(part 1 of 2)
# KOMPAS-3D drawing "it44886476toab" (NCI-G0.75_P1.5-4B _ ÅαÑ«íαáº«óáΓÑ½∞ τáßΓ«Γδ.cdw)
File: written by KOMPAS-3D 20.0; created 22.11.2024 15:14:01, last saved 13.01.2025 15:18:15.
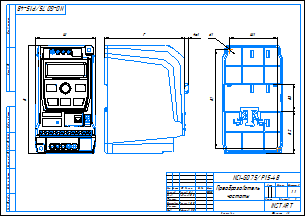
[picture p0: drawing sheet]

Sheet 1: A3, landscape

Document properties: Автор: admin; Полное имя файла: C:\Уралов Работа\Уралов (локальная)\ПЧ\! Китай 3Д-модель NCI\NCI 0.75-2.2 4B\NCI 0.75-2.2 4B.m3d

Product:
- Part/product: it44886476toab
    Масса: 2.32322
  - Body: Тело 17
      Масса: 0.0117014
  - Body: Тело 374
      Масса: 5.48304e-05
  - Body: Тело 265
      Масса: 1.32696e-05
  - Body: Тело 266
      Масса: 1.7366e-05
  - Body: Тело 267
      Масса: 1.7366e-05
  - Body: Тело 103
      Масса: 1.32696e-05
  - Body: Тело 573
      Масса: 4.06595e-05
  - Body: Тело 348
      Масса: 1.32696e-05
  - Body: Тело 270
      Масса: 1.7366e-05
  - Body: Тело 77
      Масса: 1.32696e-05
  - Body: Тело 244
      Масса: 1.65581e-05
  - Body: Тело 536
      Масса: 0.000158536
  - Body: Тело 377
      Масса: 1.65581e-05
  - Body: Тело 272
      Масса: 1.7366e-05
  - Body: Тело 273
      Масса: 5.48304e-05
  - Body: Тело 238
      Масса: 1.7366e-05
  - Body: Тело 274
      Масса: 1.7366e-05
  - Body: Тело 277
      Масса: 1.7366e-05
  - Body: Тело 530
      Масса: 5.61948e-05
  - Body: Тело 278
      Масса: 1.7366e-05
  - Body: Тело 282
      Масса: 1.7366e-05
  - Body: Тело 477
      Масса: 1.51773e-05
  - Body: Тело 526
      Масса: 5.61948e-05
  - Body: Тело 391
      Масса: 1.32696e-05
  - Body: Тело 285
      Масса: 5.48304e-05
  - Body: Тело 287
      Масса: 1.32696e-05
  - Body: Тело 290
      Масса: 0.000413213
  - Body: Тело 269
      Масса: 5.48304e-05
  - Body: Тело 292
      Масса: 1.7366e-05
  - Body: Тело 33
      Масса: 0.00516019
  - Body: Тело 252
      Масса: 5.48304e-05
  - Body: Тело 294
      Масса: 0.000413213
  - Body: Тело 297
      Масса: 3.64631e-05
  - Body: Тело 299
      Масса: 3.64028e-05
  - Body: Тело 283
      Масса: 1.7366e-05
  - Body: Тело 300
      Масса: 1.65581e-05
  - Body: Тело 303
      Масса: 1.65581e-05
  - Body: Тело 516
      Масса: 0.00507377
  - Body: Тело 384
      Масса: 5.48304e-05
  - Body: Тело 360
      Масса: 1.32696e-05
  - Body: Тело 347
      Масса: 1.32696e-05
  - Body: Тело 304
      Масса: 1.65581e-05
  - Body: Тело 307
      Масса: 0.000213463
  - Body: Тело 308
      Масса: 0.000413213
  - Body: Тело 180
      Масса: 1.32696e-05
  - Body: Тело 240
      Масса: 1.7366e-05
  - Body: Тело 309
      Масса: 1.32696e-05
  - Body: Тело 473
      Масса: 0.00425494
  - Body: Тело 311
      Масса: 5.48304e-05
  - Body: Тело 122
      Масса: 1.65581e-05
  - Body: Тело 560
      Масса: 1.65581e-05
  - Body: Тело 312
      Масса: 5.48304e-05
  - Body: Тело 317
      Масса: 1.32696e-05
  - Body: Тело 318
      Масса: 1.32696e-05
  - Body: Тело 321
      Масса: 1.32696e-05
  - Body: Тело 324
      Масса: 1.32696e-05
  - Body: Тело 480
      Масса: 1.51773e-05
  - Body: Тело 288
      Масса: 1.7366e-05
  - Body: Тело 293
      Масса: 5.48304e-05
  - Body: Тело 325
      Масса: 1.32696e-05
  - Body: Тело 99
      Масса: 1.65581e-05
  - Body: Тело 617
      Масса: 1.63919e-05
  - Body: Тело 327
      Масса: 1.32696e-05
  - Body: Тело 31
      Масса: 0.0078835
  - Body: Тело 100
      Масса: 1.65581e-05
  - Body: Тело 105
      Масса: 1.32696e-05
  - Body: Тело 328
      Масса: 1.7366e-05
  - Body: Тело 301
      Масса: 1.65581e-05
  - Body: Тело 331
      Масса: 1.7366e-05
  - Body: Тело 332
      Масса: 1.7366e-05
  - Body: Тело 446
      Масса: 0.000307437
  - Body: Тело 337
      Масса: 1.7366e-05
  - Body: Тело 338
      Масса: 1.7366e-05
  - Body: Тело 570
      Масса: 4.06595e-05
  - Body: Тело 340
      Масса: 1.32696e-05
  - Body: Тело 196
      Масса: 1.32696e-05
  - Body: Тело 357
      Масса: 1.65581e-05
  - Body: Тело 346
      Масса: 1.32696e-05
  - Body: Тело 335
      Масса: 1.32696e-05
  - Body: Тело 281
      Масса: 1.32696e-05
  - Body: Тело 362
      Масса: 1.32696e-05
  - Body: Тело 353
      Масса: 1.7366e-05
  - Body: Тело 355
      Масса: 5.48304e-05
  - Body: Тело 466
      Масса: 0.00829114
  - Body: Тело 358
      Масса: 5.48304e-05
  - Body: Тело 359
      Масса: 1.7366e-05
  - Body: Тело 286
      Масса: 1.7366e-05
  - Body: Тело 86
      Масса: 1.32696e-05
  - Body: Тело 310
      Масса: 1.7366e-05
  - Body: Тело 368
      Масса: 1.32696e-05
  - Body: Тело 370
      Масса: 1.32696e-05
  - Body: Тело 333
      Масса: 1.32696e-05
  - Body: Тело 628
      Масса: 1.51773e-05
  - Body: Тело 371
      Масса: 1.7366e-05
  - Body: Тело 75
      Масса: 1.32696e-05
  - Body: Тело 373
      Масса: 1.32696e-05
  - Body: Тело 375
      Масса: 1.32696e-05
  - Body: Тело 351
      Масса: 2.90876e-05
  - Body: Тело 76
      Масса: 1.65581e-05
  - Body: Тело 259
      Масса: 1.7366e-05
  - Body: Тело 378
      Масса: 0.000413213
  - Body: Тело 95
      Масса: 0.000935996
  - Body: Тело 372
      Масса: 1.7366e-05
  - Body: Тело 322
      Масса: 1.32696e-05
  - Body: Тело 380
      Масса: 1.32696e-05
  - Body: Тело 639
      Масса: 1.63919e-05
  - Body: Тело 385
      Масса: 1.32696e-05
  - Body: Тело 291
      Масса: 0.000213463
  - Body: Тело 386
      Масса: 1.32696e-05
  - Body: Тело 229
      Масса: 1.32696e-05
  - Body: Тело 388
      Масса: 1.32696e-05
  - Body: Тело 389
      Масса: 1.65581e-05
  - Body: Тело 93
      Масса: 3.83377e-05
  - Body: Тело 390
      Масса: 1.65581e-05
  - Body: Тело 143
      Масса: 1.32696e-05
  - Body: Тело 394
      Масса: 1.32696e-05
  - Body: Тело 395
      Масса: 1.32696e-05
  - Body: Тело 354
      Масса: 0.000213463
  - Body: Тело 396
      Масса: 1.7366e-05
  - Body: Тело 397
      Масса: 1.32696e-05
  - Body: Тело 398
      Масса: 1.65581e-05
  - Body: Тело 479
      Масса: 1.51773e-05
  - Body: Тело 402
      Масса: 1.7366e-05
  - Body: Тело 59
      Масса: 1.32696e-05
  - Body: Тело 339
      Масса: 1.32696e-05
  - Body: Тело 404
      Масса: 1.32696e-05
  - Body: Тело 89
      Масса: 0.00142218
  - Body: Тело 406
      Масса: 1.65581e-05
  - Body: Тело 393
      Масса: 1.32696e-05
  - Body: Тело 52
      Масса: 1.32696e-05
  - Body: Тело 407
      Масса: 5.48304e-05
  - Body: Тело 97
      Масса: 0.0015961
  - Body: Тело 410
      Масса: 5.48304e-05
  - Body: Тело 636
      Масса: 1.65581e-05
  - Body: Тело 412
      Масса: 1.7366e-05
  - Body: Тело 413
      Масса: 1.32696e-05
  - Body: Тело 414
      Масса: 1.32696e-05
  - Body: Тело 537
      Масса: 0.000158536
  - Body: Тело 415
      Масса: 1.7366e-05
  - Body: Тело 235
      Масса: 1.7366e-05
  - Body: Тело 419
      Масса: 1.32696e-05
  - Body: Тело 648
      Масса: 0.00426189
  - Body: Тело 420
      Масса: 1.7366e-05
  - Body: Тело 186
      Масса: 1.32696e-05
  - Body: Тело 422
      Масса: 5.48304e-05
  - Body: Тело 381
      Масса: 1.7366e-05
  - Body: Тело 423
      Масса: 1.32696e-05
  - Body: Тело 424
      Масса: 1.7366e-05
  - Body: Тело 98
      Масса: 1.65581e-05
  - Body: Тело 305
      Масса: 1.65581e-05
  - Body: Тело 425
      Масса: 1.32696e-05
  - Body: Тело 365
      Масса: 1.32696e-05
  - Body: Тело 271
      Масса: 1.32696e-05
  - Body: Тело 206
      Масса: 1.32696e-05
  - Body: Тело 429
      Масса: 0.146258
  - Body: Тело 334
      Масса: 1.7366e-05
  - Body: Тело 430
      Масса: 0.146258
  - Body: Тело 350
      Масса: 1.7366e-05
  - Body: Тело 345
      Масса: 1.32696e-05
  - Body: Тело 431
      Масса: 0.146258
  - Body: Тело 364
      Масса: 1.32696e-05
  - Body: Тело 329
      Масса: 1.32696e-05
  - Body: Тело 434
      Масса: 0.000355433
  - Body: Тело 5
      Масса: 0.000355433
  - Body: Тело 124
      Масса: 1.65581e-05
  - Body: Тело 344
      Масса: 1.32696e-05
  - Body: Тело 436
      Масса: 0.000355433
  - Body: Тело 439
      Масса: 0.00113358
  - Body: Тело 606
      Масса: 0.000137594
  - Body: Тело 323
      Масса: 1.32696e-05
  - Body: Тело 441
      Масса: 0.00113358
  - Body: Тело 442
      Масса: 0.000355433
  - Body: Тело 554
      Масса: 4.06595e-05
  - Body: Тело 444
      Масса: 0.000355433
  - Body: Тело 246
      Масса: 1.65581e-05
  - Body: Тело 445
      Масса: 0.00113358
  - Body: Тело 438
      Масса: 0.000355433
  - Body: Тело 106
      Масса: 1.32696e-05
  - Body: Тело 508
      Масса: 1.51773e-05
  - Body: Тело 577
      Масса: 1.7366e-05
  - Body: Тело 392
      Масса: 1.32696e-05
  - Body: Тело 193
      Масса: 1.32696e-05
  - Body: Тело 448
      Масса: 0.000307437
  - Body: Тело 481
      Масса: 1.51773e-05
  - Body: Тело 450
      Масса: 6.34685e-05
  - Body: Тело 222
      Масса: 1.32696e-05
  - Body: Тело 315
      Масса: 1.7366e-05
  - Body: Тело 452
      Масса: 1.63919e-05
  - Body: Тело 53
      Масса: 1.32696e-05
  - Body: Тело 401
      Масса: 1.32696e-05
  - Body: Тело 418
      Масса: 1.7366e-05
  - Body: Тело 517
      Масса: 0.00106884
  - Body: Тело 417
      Масса: 1.32696e-05
  - Body: Тело 453
      Масса: 1.63919e-05
  - Body: Тело 454
      Масса: 0.000382752
  - Body: Тело 428
      Масса: 0.146258
  - Body: Тело 455
      Масса: 1.51773e-05
  - Body: Тело 539
      Масса: 1.51773e-05
  - Body: Тело 457
      Масса: 1.51773e-05
  - Body: Тело 459
      Масса: 3.90329e-05
  - Body: Тело 557
      Масса: 0.00166679
  - Body: Тело 569
      Масса: 1.32696e-05
  - Body: Тело 578
      Масса: 1.32696e-05
  - Body: Тело 626
      Масса: 1.32696e-05
  - Body: Тело 134
      Масса: 1.32696e-05
  - Body: Тело 582
      Масса: 1.65581e-05
  - Body: Тело 203
      Масса: 1.32696e-05
  - Body: Тело 572
      Масса: 1.32696e-05
  - Body: Тело 567
      Масса: 1.32696e-05
  - Body: Тело 207
      Масса: 1.32696e-05
  - Body: Тело 645
      Масса: 1.32696e-05
  - Body: Тело 559
      Масса: 1.65581e-05
  - Body: Тело 152
      Масса: 1.32696e-05
  - Body: Тело 449
      Масса: 0.0658364
  - Body: Тело 316
      Масса: 1.32696e-05
  - Body: Тело 376
      Масса: 1.32696e-05
  - Body: Тело 575
      Масса: 1.32696e-05
  - Body: Тело 576
      Масса: 1.32696e-05
  - Body: Тело 85
      Масса: 1.32696e-05
  - Body: Тело 574
      Масса: 4.06595e-05
  - Body: Тело 399
      Масса: 1.32696e-05
  - Body: Тело 320
      Масса: 1.32696e-05
  - Body: Тело 275
      Масса: 1.7366e-05
  - Body: Тело 213
      Масса: 1.32696e-05
  - Body: Тело 625
      Масса: 1.32696e-05
  - Body: Тело 644
      Масса: 0.000158536
  - Body: Тело 584
      Масса: 4.06595e-05
  - Body: Тело 70
      Масса: 1.65581e-05
  - Body: Тело 588
      Масса: 1.32696e-05
  - Body: Тело 276
      Масса: 1.7366e-05
  - Body: Тело 363
      Масса: 1.32696e-05
  - Body: Тело 474
      Масса: 1.51773e-05
  - Body: Тело 548
      Масса: 2.98222e-05
  - Body: Тело 409
      Масса: 5.48304e-05
  - Body: Тело 472
      Масса: 0.00329327
  - Body: Тело 533
      Масса: 5.61948e-05
  - Body: Тело 647
      Масса: 0.00426189
  - Body: Тело 586
      Масса: 1.32696e-05
  - Body: Тело 262
      Масса: 1.7366e-05
  - Body: Тело 562
      Масса: 0.000382752
  - Body: Тело 379
      Масса: 1.32696e-05
  - Body: Тело 632
      Масса: 1.51773e-05
  - Body: Тело 565
      Масса: 4.06595e-05
  - Body: Тело 118
      Масса: 0.000413213
  - Body: Тело 597
      Масса: 7.12116e-06
  - Body: Тело 613
      Масса: 1.63919e-05
  - Body: Тело 387
      Масса: 1.32696e-05
  - Body: Тело 593
      Масса: 1.32696e-05
  - Body: Тело 408
      Масса: 5.48304e-05
  - Body: Тело 109
      Масса: 1.32696e-05
  - Body: Тело 163
      Масса: 1.32696e-05
  - Body: Тело 488
      Масса: 1.51773e-05
  - Body: Тело 367
      Масса: 1.32696e-05
  - Body: Тело 411
      Масса: 5.48304e-05
  - Body: Тело 583
      Масса: 4.06595e-05
  - Body: Тело 598
      Масса: 7.12116e-06
  - Body: Тело 551
      Масса: 0.000255388
  - Body: Тело 405
      Масса: 1.32696e-05
  - Body: Тело 619
      Масса: 1.32696e-05
  - Body: Тело 361
      Масса: 1.32696e-05
  - Body: Тело 589
      Масса: 1.32696e-05
  - Body: Тело 499
      Масса: 1.51773e-05
  - Body: Тело 440
      Масса: 0.000355433
  - Body: Тело 640
      Масса: 1.63919e-05
  - Body: Тело 150
      Масса: 1.32696e-05
  - Body: Тело 568
      Масса: 1.32696e-05
  - Body: Тело 194
      Масса: 1.32696e-05
  - Body: Тело 251
      Масса: 1.7366e-05
  - Body: Тело 342
      Масса: 0.00166679
  - Body: Тело 604
      Масса: 5.61948e-05
  - Body: Тело 650
      Масса: 0.00426189
  - Body: Тело 161
      Масса: 1.32696e-05
  - Body: Тело 611
      Масса: 0.000158536
  - Body: Тело 210
      Масса: 1.32696e-05
  - Body: Тело 540
      Масса: 1.51773e-05
  - Body: Тело 296
      Масса: 3.6965e-05
  - Body: Тело 601
      Масса: 5.61948e-05
  - Body: Тело 484
      Масса: 0.000158536
  - Body: Тело 622
      Масса: 1.32696e-05
  - Body: Тело 527
      Масса: 0.000141095
  - Body: Тело 624
      Масса: 1.32696e-05
  - Body: Тело 121
      Масса: 0.000413213
  - Body: Тело 600
      Масса: 5.61948e-05
  - Body: Тело 603
      Масса: 5.61948e-05
  - Body: Тело 607
      Масса: 1.32696e-05
  - Body: Тело 289
      Масса: 1.7366e-05
  - Body: Тело 471
      Масса: 0.00329327
  - Body: Тело 313
      Масса: 1.7366e-05
  - Body: Тело 591
      Масса: 7.12116e-06
  - Body: Тело 356
      Масса: 1.65581e-05
  - Body: Тело 306
      Масса: 1.65581e-05
  - Body: Тело 541
      Масса: 0.000158536
  - Body: Тело 511
      Масса: 1.51773e-05
  - Body: Тело 160
      Масса: 1.32696e-05
  - Body: Тело 566
      Масса: 1.32696e-05
  - Body: Тело 563
      Масса: 4.06595e-05
  - Body: Тело 638
      Масса: 1.7366e-05
  - Body: Тело 489
      Масса: 1.51773e-05
  - Body: Тело 456
      Масса: 1.51773e-05
  - Body: Тело 485
      Масса: 0.000158536
  - Body: Тело 284
      Масса: 1.7366e-05
  - Body: Тело 138
      Масса: 2.23009e-05
  - Body: Тело 225
      Масса: 1.32696e-05
  - Body: Тело 546
      Масса: 0.000255388
  - Body: Тело 113
      Масса: 0.000413213
  - Body: Тело 642
      Масса: 3.90329e-05
  - Body: Тело 618
      Масса: 1.63919e-05
  - Body: Тело 525
      Масса: 0.000213463
  - Body: Тело 164
      Масса: 1.32696e-05
  - Body: Тело 253
      Масса: 1.7366e-05
  - Body: Тело 561
      Масса: 1.65581e-05
  - Body: Тело 594
      Масса: 1.32696e-05
  - Body: Тело 482
      Масса: 1.51773e-05
  - Body: Тело 81
      Масса: 1.32696e-05
  - Body: Тело 280
      Масса: 1.32696e-05
  - Body: Тело 494
      Масса: 1.51773e-05
  - Body: Тело 641
      Масса: 3.90329e-05
  - Body: Тело 564
      Масса: 4.06595e-05
  - Body: Тело 633
      Масса: 1.51773e-05
  - Body: Тело 518
      Масса: 0.00166679
  - Body: Тело 620
      Масса: 1.7366e-05
  - Body: Тело 497
      Масса: 1.51773e-05
  - Body: Тело 151
      Масса: 1.65581e-05
  - Body: Тело 302
      Масса: 1.65581e-05
  - Body: Тело 110
      Масса: 1.32696e-05
  - Body: Тело 646
      Масса: 0.000137594
  - Body: Тело 264
      Масса: 1.7366e-05
  - Body: Тело 635
      Масса: 1.65581e-05
  - Body: Тело 608
      Масса: 0.00166679
  - Body: Тело 460
      Масса: 3.90329e-05
  - Body: Тело 403
      Масса: 1.7366e-05
  - Body: Тело 612
      Масса: 0.000158536
  - Body: Тело 492
      Масса: 1.51773e-05
  - Body: Тело 139
      Масса: 0.000194606
  - Body: Тело 400
      Масса: 1.7366e-05
  - Body: Тело 605
      Масса: 5.61948e-05
  - Body: Тело 623
      Масса: 1.32696e-05
  - Body: Тело 117
      Масса: 0.000413213
  - Body: Тело 185
      Масса: 1.32696e-05
  - Body: Тело 631
      Масса: 1.51773e-05
  - Body: Тело 580
      Масса: 1.32696e-05
  - Body: Тело 349
      Масса: 1.7366e-05
  - Body: Тело 621
      Масса: 1.32696e-05
  - Body: Тело 627
      Масса: 0.000255388
  - Body: Тело 531
      Масса: 5.61948e-05
  - Body: Тело 649
      Масса: 0.00426189
  - Body: Тело 585
      Масса: 4.06595e-05
  - Body: Тело 236
      Масса: 1.7366e-05
  - Body: Тело 513
      Масса: 1.51773e-05
  - Body: Тело 426
      Масса: 1.32696e-05
  - Body: Тело 341
      Масса: 0.00166679
  - Body: Тело 470
      Масса: 0.00329329
  - Body: Тело 382
      Масса: 5.48304e-05
  - Body: Тело 227
      Масса: 1.32696e-05
  - Body: Тело 476
      Масса: 1.51773e-05
  - Body: Тело 538
      Масса: 1.51773e-05
  - Body: Тело 596
      Масса: 1.32696e-05
  - Body: Тело 609
      Масса: 1.7366e-05
  - Body: Тело 610
      Масса: 0.00166679
  - Body: Тело 263
      Масса: 1.7366e-05
  - Body: Тело 629
      Масса: 1.51773e-05
  - Body: Тело 336
      Масса: 3.64028e-05
  - Body: Тело 495
      Масса: 1.51773e-05
  - Body: Тело 168
      Масса: 1.32696e-05
  - Body: Тело 298
      Масса: 3.64495e-05
  - Body: Тело 279
      Масса: 1.32696e-05
  - Body: Тело 72
      Масса: 1.65581e-05
  - Body: Тело 500
      Масса: 1.51773e-05
  - Body: Тело 505
      Масса: 1.51773e-05
  - Body: Тело 558
      Масса: 0.00726683
  - Body: Тело 630
      Масса: 1.51773e-05
  - Body: Тело 602
      Масса: 5.61948e-05
  - Body: Тело 556
      Масса: 0.00166679
  - Body: Тело 555
      Масса: 0.00166679
  - Body: Тело 634
      Масса: 1.51773e-05
  - Body: Тело 435
      Масса: 0.00113358
  - Body: Тело 416
      Масса: 1.7366e-05
  - Body: Тело 190
      Масса: 1.32696e-05
  - Body: Тело 330
      Масса: 1.7366e-05
  - Body: Тело 28
      Масса: 0.00135688
  - Body: Тело 553
      Масса: 4.06595e-05
  - Body: Тело 176
      Масса: 1.32696e-05
  - Body: Тело 552
      Масса: 4.06595e-05
  - Body: Тело 534
      Масса: 1.32696e-05
  - Body: Тело 595
      Масса: 1.32696e-05
  - Body: Тело 23
      Масса: 0.0243258
  - Body: Тело 247
      Масса: 1.7366e-05
  - Body: Тело 314
      Масса: 1.7366e-05
  - Body: Тело 126
      Масса: 0.000512664
  - Body: Тело 157
      Масса: 1.32696e-05
  - Body: Тело 550
      Масса: 0.000255388
  - Body: Тело 32
      Масса: 0.0135217
  - Body: Тело 592
      Масса: 7.12116e-06
  - Body: Тело 366
      Масса: 1.7366e-05
  - Body: Тело 504
      Масса: 1.51773e-05
  - Body: Тело 258
      Масса: 1.7366e-05
  - Body: Тело 421
      Масса: 1.7366e-05
  - Body: Тело 35
      Масса: 0.262997
  - Body: Тело 204
      Масса: 1.32696e-05
  - Body: Тело 549
      Масса: 0.000255388
  - Body: Тело 257
      Масса: 1.7366e-05
  - Body: Тело 614
      Масса: 1.63919e-05
  - Body: Тело 547
      Масса: 0.000255388
  - Body: Тело 41
      Масса: 0.0119524
  - Body: Тело 71
      Масса: 1.65581e-05
  - Body: Тело 506
      Масса: 1.51773e-05
  - Body: Тело 545
      Масса: 1.51773e-05
  - Body: Тело 145
      Масса: 1.32696e-05
  - Body: Тело 461
      Масса: 0.000404362
  - Body: Тело 502
      Масса: 1.51773e-05
  - Body: Тело 352
      Масса: 2.90876e-05
  - Body: Тело 120
      Масса: 0.000413213
  - Body: Тело 295
      Масса: 1.65581e-05
  - Body: Тело 544
      Масса: 0.000158536
  - Body: Тело 469
      Масса: 0.0113891
  - Body: Тело 146
      Масса: 1.32696e-05
  - Body: Тело 149
      Масса: 1.32696e-05
  - Body: Тело 615
      Масса: 1.63919e-05
  - Body: Тело 543
      Масса: 0.000158536
  - Body: Тело 542
      Масса: 0.000158536
  - Body: Тело 462
      Масса: 0.000404362
  - Body: Тело 616
      Масса: 1.63919e-05
  - Body: Тело 343
      Масса: 0.00166679
  - Body: Тело 532
      Масса: 5.61948e-05
  - Body: Тело 493
      Масса: 1.51773e-05
  - Body: Тело 529
      Масса: 5.61948e-05
  - Body: Тело 579
      Масса: 0.00017125
  - Body: Тело 200
      Масса: 1.32696e-05
  - Body: Тело 239
      Масса: 5.48304e-05
  - Body: Тело 443
      Масса: 0.00113358
  - Body: Тело 216
      Масса: 0.000280294
  - Body: Тело 468
      Масса: 0.0253857
  - Body: Тело 64
      Масса: 1.65581e-05
  - Body: Тело 528
      Масса: 0.000141095
  - Body: Тело 599
      Масса: 7.12116e-06
  - Body: Тело 590
      Масса: 1.32696e-05
  - Body: Тело 191
      Масса: 1.32696e-05
  - Body: Тело 523
      Масса: 0.000255388
  - Body: Тело 458
      Масса: 1.51773e-05
  - Body: Тело 319
      Масса: 1.32696e-05
  - Body: Тело 49
      Масса: 0.00944
  - Body: Тело 522
      Масса: 1.65581e-05
  - Body: Тело 521
      Масса: 1.32696e-05
  - Body: Тело 571
      Масса: 0.00166679
  - Body: Тело 509
      Масса: 1.51773e-05
  - Body: Тело 326
      Масса: 1.32696e-05
  - Body: Тело 520
      Масса: 5.48304e-05
  - Body: Тело 427
      Масса: 1.32696e-05
  - Body: Тело 519
      Масса: 1.7366e-05
  - Body: Тело 637
      Масса: 1.51773e-05
  - Body: Тело 524
      Масса: 1.65581e-05
  - Body: Тело 432
      Масса: 0.000118347
  - Body: Тело 487
      Масса: 1.65581e-05
  - Body: Тело 510
      Масса: 1.51773e-05
  - Body: Тело 515
      Масса: 0.00507372
  - Body: Тело 512
      Масса: 1.51773e-05
  - Body: Тело 155
      Масса: 1.32696e-05
  - Body: Тело 587
      Масса: 1.32696e-05
  - Body: Тело 174
      Масса: 1.65581e-05
  - Body: Тело 507
      Масса: 1.51773e-05
  - Body: Тело 12
      Масса: 0.000703761
  - Body: Тело 187
      Масса: 1.32696e-05
  - Body: Тело 447
      Масса: 0.000307437
  - Body: Тело 503
      Масса: 1.51773e-05
  - Body: Тело 501
      Масса: 1.51773e-05
  - Body: Тело 369
      Масса: 1.32696e-05
  - Body: Тело 60
      Масса: 1.32696e-05
  - Body: Тело 498
      Масса: 1.51773e-05
  - Body: Тело 535
      Масса: 1.52051e-05
  - Body: Тело 437
      Масса: 0.00113358
  - Body: Тело 496
      Масса: 1.51773e-05
  - Body: Тело 433
      Масса: 0.000118347
  - Body: Тело 491
      Масса: 1.65581e-05
  - Body: Тело 490
      Масса: 1.51773e-05
  - Body: Тело 581
      Масса: 1.65581e-05
  - Body: Тело 486
      Масса: 0.000158536
  - Body: Тело 483
      Масса: 1.51773e-05
  - Body: Тело 514
      Масса: 1.51773e-05
  - Body: Тело 643
      Масса: 0.000158536
  - Body: Тело 125
      Масса: 1.65581e-05
  - Body: Тело 383
      Масса: 0.000340816
  - Body: Тело 465
      Масса: 0.00829114
  - Body: Тело 478
      Масса: 1.51773e-05
  - Body: Тело 451
      Масса: 6.34685e-05
  - Body: Тело 475
      Масса: 1.51773e-05
  - Body: Тело 467
      Масса: 0.00436982
  - Body: Тело 268
      Масса: 5.48304e-05
  - Body: Тело 464
      Масса: 0.00829425
  - Body: Тело 226
      Масса: 0.000413213
  - Body: Тело 463
      Масса: 0.000404362
  - Body: Тело 170
      Масса: 1.32696e-05
  - Body: Тело 261
      Масса: 3.83377e-05
  - Body: Тело 260
      Масса: 1.7366e-05
  - Body: Тело 167
      Масса: 1.32696e-05
  - Body: Тело 256
      Масса: 1.7366e-05
  - Body: Тело 119
      Масса: 0.000413213
  - Body: Тело 255
      Масса: 1.7366e-05
  - Body: Тело 254
      Масса: 1.32696e-05
  - Body: Тело 250
      Масса: 1.7366e-05
  - Body: Тело 249
      Масса: 1.7366e-05
  - Body: Тело 248
      Масса: 1.7366e-05
  - Body: Тело 19
      Масса: 0.0117014
  - Body: Тело 114
      Масса: 0.000413213
  - Body: Тело 234
      Масса: 1.7366e-05
  - Body: Тело 245
      Масса: 1.65581e-05
  - Body: Тело 243
      Масса: 1.65581e-05
  - Body: Тело 242
      Масса: 1.65581e-05
  - Body: Тело 65
      Масса: 1.65581e-05
  - Body: Тело 241
      Масса: 0.000424983
  - Body: Тело 141
      Масса: 0.000213463
  - Body: Тело 237
      Масса: 1.7366e-05
  - Body: Тело 1
      Масса: 0.00113358
  - Body: Тело 233
      Масса: 1.7366e-05
  - Body: Тело 232
      Масса: 5.48304e-05
  - Body: Тело 231
      Масса: 0.00398049
  - Body: Тело 230
      Масса: 1.32696e-05
  - Body: Тело 184
      Масса: 1.32696e-05
  - Body: Тело 228
      Масса: 1.32696e-05
  - Body: Тело 224
      Масса: 1.32696e-05
  - Body: Тело 162
      Масса: 1.65581e-05
  - Body: Тело 223
      Масса: 1.32696e-05
  - Body: Тело 221
      Масса: 1.65581e-05
  - Body: Тело 220
      Масса: 1.32696e-05
  - Body: Тело 219
      Масса: 1.32696e-05
  - Body: Тело 218
      Масса: 1.32696e-05
  - Body: Тело 217
      Масса: 1.32696e-05
  - Body: Тело 215
      Масса: 1.65581e-05
  - Body: Тело 9
      Масса: 0.000703761
  - Body: Тело 214
      Масса: 1.32696e-05
  - Body: Тело 212
      Масса: 1.32696e-05
  - Body: Тело 211
      Масса: 1.32696e-05
  - Body: Тело 209
      Масса: 1.32696e-05
  - Body: Тело 208
      Масса: 1.7366e-05
  - Body: Тело 205
      Масса: 1.32696e-05
  - Body: Тело 202
      Масса: 1.32696e-05
  - Body: Тело 201
      Масса: 1.32696e-05
  - Body: Тело 29
      Масса: 0.00135688
  - Body: Тело 199
      Масса: 1.32696e-05
  - Body: Тело 198
      Масса: 1.32696e-05
  - Body: Тело 197
      Масса: 1.32696e-05
  - Body: Тело 195
      Масса: 1.32696e-05
  - Body: Тело 192
      Масса: 1.32696e-05
  - Body: Тело 189
      Масса: 1.32696e-05
  - Body: Тело 188
      Масса: 1.32696e-05
  - Body: Тело 183
      Масса: 1.32696e-05
  - Body: Тело 182
      Масса: 1.32696e-05
  - Body: Тело 181
      Масса: 1.32696e-05
  - Body: Тело 179
      Масса: 1.32696e-05
  - Body: Тело 178
      Масса: 1.32696e-05
  - Body: Тело 44
      Масса: 0.0119524
  - Body: Тело 50
      Масса: 0.00101975
  - Body: Тело 177
      Масса: 1.32696e-05
  - Body: Тело 175
      Масса: 1.32696e-05
  - Body: Тело 45
      Масса: 0.0267013
  - Body: Тело 137
      Масса: 1.32696e-05
  - Body: Тело 173
      Масса: 1.32696e-05
  - Body: Тело 172
      Масса: 1.65581e-05
  - Body: Тело 153
      Масса: 1.32696e-05
  - Body: Тело 171
      Масса: 1.32696e-05
  - Body: Тело 169
      Масса: 1.32696e-05
  - Body: Тело 140
      Масса: 0.000213463
  - Body: Тело 166
      Масса: 1.32696e-05
  - Body: Тело 165
      Масса: 1.65581e-05
  - Body: Тело 159
      Масса: 1.32696e-05
  - Body: Тело 116
      Масса: 0.000413213
  - Body: Тело 158
      Масса: 1.32696e-05
  - Body: Тело 156
      Масса: 1.32696e-05
  - Body: Тело 154
      Масса: 1.32696e-05
  - Body: Тело 148
      Масса: 1.32696e-05
  - Body: Тело 147
      Масса: 1.32696e-05
  - Body: Тело 24
      Масса: 0.0110484
  - Body: Тело 62
      Масса: 1.32696e-05
  - Body: Тело 144
      Масса: 1.32696e-05
  - Body: Тело 142
      Масса: 0.000213463
  - Body: Тело 136
      Масса: 1.32696e-05
  - Body: Тело 135
      Масса: 1.32696e-05
  - Body: Тело 38
      Масса: 0.00631989
  - Body: Тело 133
      Масса: 1.32696e-05
  - Body: Тело 132
      Масса: 1.32696e-05
  - Body: Тело 131
      Масса: 1.32696e-05
  - Body: Тело 16
      Масса: 0.000703761
  - Body: Тело 130
      Масса: 1.32696e-05
  - Body: Тело 112
      Масса: 0.000413213
  - Body: Тело 129
      Масса: 1.32696e-05
  - Body: Тело 128
      Масса: 1.32696e-05
  - Body: Тело 127
      Масса: 1.32696e-05
  - Body: Тело 123
      Масса: 1.65581e-05
  - Body: Тело 115
      Масса: 0.000413213
  - Body: Тело 111
      Масса: 0.000194606
  - Body: Тело 108
      Масса: 1.32696e-05
  - Body: Тело 107
      Масса: 1.32696e-05
  - Body: Тело 104
      Масса: 1.32696e-05
  - Body: Тело 102
      Масса: 1.32696e-05
  - Body: Тело 90
      Масса: 0.000966482
  - Body: Тело 101
      Масса: 1.32696e-05
  - Body: Тело 96
      Масса: 0.00181049
  - Body: Тело 94
      Масса: 0.00554276
  - Body: Тело 92
      Масса: 3.83377e-05
  - Body: Тело 91
      Масса: 0.0246688
  - Body: Тело 15
      Масса: 0.000703761
  - Body: Тело 88
      Масса: 0.000873873
  - Body: Тело 87
      Масса: 0.000966482
  - Body: Тело 84
      Масса: 1.32696e-05
  - Body: Тело 83
      Масса: 1.32696e-05
  - Body: Тело 82
      Масса: 1.32696e-05
  - Body: Тело 80
      Масса: 1.32696e-05
  - Body: Тело 79
      Масса: 1.32696e-05
  - Body: Тело 78
      Масса: 1.65581e-05
  - Body: Тело 74
      Масса: 1.65581e-05
  - Body: Тело 48
      Масса: 0.00853877
  - Body: Тело 73
      Масса: 1.65581e-05
  - Body: Тело 69
      Масса: 1.65581e-05
  - Body: Тело 68
      Масса: 1.65581e-05
  - Body: Тело 67
      Масса: 1.65581e-05
  - Body: Тело 66
      Масса: 1.65581e-05
  - Body: Тело 63
      Масса: 1.65581e-05
  - Body: Тело 57
      Масса: 1.32696e-05
  - Body: Тело 61
      Масса: 1.32696e-05
  - Body: Тело 58
      Масса: 1.32696e-05
  - Body: Тело 56
      Масса: 1.32696e-05
  - Body: Тело 55
      Масса: 1.32696e-05
  - Body: Тело 54
      Масса: 1.32696e-05
  - Body: Тело 51
      Масса: 1.32696e-05
  - Body: Тело 47
      Масса: 0.551587
  - Body: Тело 46
      Масса: 0.0119034
  - Body: Тело 43
      Масса: 0.0119524
  - Body: Тело 42
      Масса: 0.0119524
  - Body: Тело 40
      Масса: 0.0119524
  - Body: Тело 39
      Масса: 0.0119524
  - Body: Тело 37
      Масса: 0.0343584
  - Body: Тело 36
      Масса: 0.0668131
  - Body: Тело 34
      Масса: 0.00831628
  - Body: Тело 30
      Масса: 0.000935996
  - Body: Тело 27
      Масса: 0.00135688
  - Body: Тело 26
      Масса: 0.00135688
  - Body: Тело 25
      Масса: 0.00135688
  - Body: Тело 22
      Масса: 0.0636504
  - Body: Тело 21
      Масса: 0.0864411
  - Body: Тело 20
      Масса: 0.120334
  - Body: Тело 18
      Масса: 0.0117014
  - Body: Тело 14
      Масса: 0.000703761
  - Body: Тело 13
      Масса: 0.000703761
  - Body: Тело 11
      Масса: 0.000703761
  - Body: Тело 10
      Масса: 0.0160396
  - Body: Тело 8
      Масса: 0.000703761
  - Body: Тело 7
      Масса: 0.000703761
  - Body: Тело 6
      Масса: 0.000355433
  - Body: Тело 4
      Масса: 0.000355433
  - Body: Тело 3
      Масса: 0.00113358
  - Body: Тело 2
      Масса: 0.00113358

Title block, sheet 1: Наименование: Преобразователь / частоты; designation: NCI-G0.75/P1.5-4B; Количество листов документа: 1; organisation: INSTART; cell 10: Согласовано; Форматы листов документа: A3; stored path: P:\INSTART\Технический отдел\ОР\Прочие задачи\КД на номенклатурный ряд\КД на типоразмеры ПЧ\NCI\NCI-G0.75_P1.5-4B\NCI-G0.75_P1.5-4B _ Преобразователь частоты.cdw; Разработал: Уралов Д.А.; Проверил: Андреев Н.В.; Подписал: Смелков Ж.Е.; Утвердил: Ефремов И.Н.; Разработал, date: 13.01.25

Views: Вид 1
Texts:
  Кривая без истории:10000
  Кривая без истории:10001
  Кривая без истории:10002
  Кривая без истории:10003
  Кривая без истории:10004
  Кривая без истории:10005
  Кривая без истории:10006
  Кривая без истории:10007
  Кривая без истории:10008
  Кривая без истории:10009
  Кривая без истории:10010
  Кривая без истории:10011
  Кривая без истории:10012
  Кривая без истории:10013
  Кривая без истории:10014
  Кривая без истории:10015
  Кривая без истории:10016
  Кривая без истории:10017
  Кривая без истории:10018
  Кривая без истории:10019
  Кривая без истории:10020
  Кривая без истории:10021
  Кривая без истории:10022
  Кривая без истории:10023
  Кривая без истории:10024
  Кривая без истории:10025
  Кривая без истории:10026
  Кривая без истории:10027
  Кривая без истории:10028
  Кривая без истории:10029
  Кривая без истории:10030
  Кривая без истории:10031
  Кривая без истории:10032
  Кривая без истории:10033
  Кривая без истории:10034
  Кривая без истории:10035
  Кривая без истории:10036
  Кривая без истории:10037
  Кривая без истории:10038
  Кривая без истории:10039
  Кривая без истории:10040
  Кривая без истории:10041
  Кривая без истории:10042
  Кривая без истории:10043
  Кривая без истории:10044
  Кривая без истории:10045
  Кривая без истории:10046
  Кривая без истории:10047
  Кривая без истории:10048
  Кривая без истории:10049
  Кривая без истории:10050
  Кривая без истории:10051
  Кривая без истории:10052
  Кривая без истории:10053
  Кривая без истории:10054
  Кривая без истории:10055
  Кривая без истории:10056
  Кривая без истории:10057
  Кривая без истории:10058
  Кривая без истории:10059
  Кривая без истории:10060
  Кривая без истории:10061
  Кривая без истории:10062
  Кривая без истории:10063
  Кривая без истории:10064
  Кривая без истории:10065
  Кривая без истории:10066
  Кривая без истории:10067
  Кривая без истории:10068
  Кривая без истории:10069
  Кривая без истории:10070
  Кривая без истории:10071
  Кривая без истории:10072
  Кривая без истории:10073
  Кривая без истории:10074
  Кривая без истории:10075
  Кривая без истории:10076
  Кривая без истории:10077
  Кривая без истории:10078
  Кривая без истории:10079
  Кривая без истории:10080
  Кривая без истории:10081
  Кривая без истории:10082
  Кривая без истории:10083
  Кривая без истории:10084
  Кривая без истории:10085
  Кривая без истории:10086
  Кривая без истории:10087
  Кривая без истории:10088
  Кривая без истории:10089
  Кривая без истории:10090
  Кривая без истории:10091
  Кривая без истории:10092
  Кривая без истории:10093
  Кривая без истории:10094
  Кривая без истории:10095
  Кривая без истории:10096
  Кривая без истории:10097
  Кривая без истории:10098
  Кривая без истории:10099
  Кривая без истории:10100
  Кривая без истории:10101
  Кривая без истории:10102
  Кривая без истории:10103
  Кривая без истории:10104
  Кривая без истории:10105
  Кривая без истории:10106
  Кривая без истории:10107
  Кривая без истории:10108
  Кривая без истории:10109
  Кривая без истории:10110
  Кривая без истории:10111
  Кривая без истории:10112
  Кривая без истории:10113
  Кривая без истории:10114
  Кривая без истории:10115
  Кривая без истории:10116
  Кривая без истории:10117
  Кривая без истории:10118
  Кривая без истории:10119
  Кривая без истории:10120
  Кривая без истории:10121
  Кривая без истории:10122
  Кривая без истории:10123
  Кривая без истории:10124
  Кривая без истории:10125
  Кривая без истории:10126
  Кривая без истории:10127
  Кривая без истории:10128
  Кривая без истории:10129
  Кривая без истории:10130
  Кривая без истории:10131
  Кривая без истории:10132
  Кривая без истории:10133
  Кривая без истории:10134
  Кривая без истории:10135
  Кривая без истории:10136
  Кривая без истории:10137
  Кривая без истории:10138
  Кривая без истории:10139
  Кривая без истории:10140
  Кривая без истории:10141
  Кривая без истории:10142
  Кривая без истории:10143
  Кривая без истории:10144
  Кривая без истории:10145
  Кривая без истории:10146
  Кривая без истории:10147
  Кривая без истории:10148
  Кривая без истории:10149
  Кривая без истории:10150
  Кривая без истории:10151
  Кривая без истории:10152
  Кривая без истории:10153
  Кривая без истории:10154
  Кривая без истории:10155
  Кривая без истории:10156
  Кривая без истории:10157
  Кривая без истории:10158
  Кривая без истории:10159
  Кривая без истории:10160
  Кривая без истории:10161
  Кривая без истории:10162
  Кривая без истории:10163
  Кривая без истории:10164
  Кривая без истории:10165
  Кривая без истории:10166
  Кривая без истории:10167
  Кривая без истории:10168
  Кривая без истории:10169
  Кривая без истории:10170
  Кривая без истории:10171
  Кривая без истории:10172
  Кривая без истории:10173
  Кривая без истории:10174
  Кривая без истории:10175
  Кривая без истории:10176
  Кривая без истории:10177
  Кривая без истории:10178
  Кривая без истории:10179
  Кривая без истории:10180
  Кривая без истории:10181
  Кривая без истории:10182
  Кривая без истории:10183
  Кривая без истории:10184
  Кривая без истории:10185
  Кривая без истории:10186
  Кривая без истории:10187
  Кривая без истории:10188
  Кривая без истории:10189
  Кривая без истории:10190
  Кривая без истории:10191
  Кривая без истории:10192
  Кривая без истории:10193
  Кривая без истории:10194
  Кривая без истории:10195
  Кривая без истории:10196
  Кривая без истории:10197
  Кривая без истории:10198
  Кривая без истории:10199
  Кривая без истории:10200
  Кривая без истории:10201
  Кривая без истории:10202
  Кривая без истории:10203
  Кривая без истории:10204
  Кривая без истории:10205
  Кривая без истории:10206
  Кривая без истории:10207
  Кривая без истории:10208
  Кривая без истории:10209
  Кривая без истории:10210
  Кривая без истории:10211
  Кривая без истории:10212
  Кривая без истории:10213
  Кривая без истории:10214
  Кривая без истории:10215
  Кривая без истории:10216
  Кривая без истории:10217
  Кривая без истории:10218
  Кривая без истории:10219
  Кривая без истории:10220
  Кривая без истории:10221
  Кривая без истории:10222
  Кривая без истории:10223
  Кривая без истории:10224
  Кривая без истории:10225
  Кривая без истории:10226
  Кривая без истории:10227
  Кривая без истории:10228
  Кривая без истории:10229
  Кривая без истории:10230
  Кривая без истории:10231
  Кривая без истории:10232
  Кривая без истории:10233
  Кривая без истории:10234
  Кривая без истории:10235
  Кривая без истории:10236
  Кривая без истории:10237
  Кривая без истории:10238
  Кривая без истории:10239
  Кривая без истории:10240
  Кривая без истории:10241
  Кривая без истории:10242
  Кривая без истории:10243
  Кривая без истории:10244
  Кривая без истории:10245
  Кривая без истории:10246
  Кривая без истории:10247
  Кривая без истории:10248
  Кривая без истории:10249
  Кривая без истории:10250
  Кривая без истории:10251
  Кривая без истории:10252
  Кривая без истории:10253
  Кривая без истории:10254
  Кривая без истории:10255
  Кривая без истории:10256
  Кривая без истории:10257
  Кривая без истории:10258
  Кривая без истории:10259
  Кривая без истории:10260
  Кривая без истории:10261
  Кривая без истории:10262
  Кривая без истории:10263
  Кривая без истории:10264
  Кривая без истории:10265
  Кривая без истории:10266
  Кривая без истории:10267
  Кривая без истории:10268
  Кривая без истории:10269
  Кривая без истории:10270
  Кривая без истории:10271
  Кривая без истории:10272
  Кривая без истории:10273
  Кривая без истории:10274
  Кривая без истории:10275
  Кривая без истории:10276
  Кривая без истории:10277
  Кривая без истории:10278
  Кривая без истории:10279
  Кривая без истории:10280
  Кривая без истории:10281
  Кривая без истории:10282
  Кривая без истории:10283
  Кривая без истории:10284
  Кривая без истории:10285
  Кривая без истории:10286
  Кривая без истории:10287
  Кривая без истории:10288
  Кривая без истории:10289
  Кривая без истории:10290
  Кривая без истории:10291
  Кривая без истории:10292
  Кривая без истории:10293
  Кривая без истории:10294
  Кривая без истории:10295
  Кривая без истории:10296
  Кривая без истории:10297
  Кривая без истории:10298
  Кривая без истории:10299
  Кривая без истории:10300
  Кривая без истории:10301
  Кривая без истории:10302
  Кривая без истории:10303
  Кривая без истории:10304
  Кривая без истории:10305
  Кривая без истории:10306
  Кривая без истории:10307
  Кривая без истории:10308
  Кривая без истории:10309
  Кривая без истории:10310
  Кривая без истории:10311
  Кривая без истории:10312
  Кривая без истории:10313
  Кривая без истории:10314
  Кривая без истории:10315
  Кривая без истории:10316
  Кривая без истории:10317
  Кривая без истории:10318
  Кривая без истории:10319
  Кривая без истории:10320
  Кривая без истории:10321
  Кривая без истории:10322
  Кривая без истории:10323
  Кривая без истории:10324
  Кривая без истории:10325
  Кривая без истории:10326
  Кривая без истории:10327
  Кривая без истории:10328
  Кривая без истории:10329
  Кривая без истории:10330
  Кривая без истории:10331
  Кривая без истории:10332
  Кривая без истории:10333
  Кривая без истории:10334
  Кривая без истории:10335
  Кривая без истории:10336
  Кривая без истории:10337
  Кривая без истории:10338
  Кривая без истории:10339
  Кривая без истории:10340
  Кривая без истории:10341
  Кривая без истории:10342
  Кривая без истории:10343
  Кривая без истории:10344
  Кривая без истории:10345
  Кривая без истории:10346
  Кривая без истории:10347
  Кривая без истории:10348
  Кривая без истории:10349
  Кривая без истории:10350
  Кривая без истории:10351
  Кривая без истории:10352
  Кривая без истории:10353
  Кривая без истории:10354
  Кривая без истории:10355
  Кривая без истории:10356
  Кривая без истории:10357
  Кривая без истории:10358
  Кривая без истории:10359
  Кривая без истории:10360
  Кривая без истории:10361
  Кривая без истории:10362
  Кривая без истории:10363
  Кривая без истории:10364
  Кривая без истории:10365
  Кривая без истории:10366
  Кривая без истории:10367
  Кривая без истории:10368
  Кривая без истории:10369
  Кривая без истории:10370
  Кривая без истории:10371
  Кривая без истории:10372
  Кривая без истории:10373
  Кривая без истории:10374
  Кривая без истории:10375
  Кривая без истории:10376
  Кривая без истории:10377
  Кривая без истории:10378
  Кривая без истории:10379
  Кривая без истории:10380
  Кривая без истории:10381
  Кривая без истории:10382
  Кривая без истории:10383
  Кривая без истории:10384
  Кривая без истории:10385
  Кривая без истории:10386
  Кривая без истории:10387
  Кривая без истории:10388
  Кривая без истории:10389
  Кривая без истории:10390
  Кривая без истории:10391
  Кривая без истории:10392
  Кривая без истории:10393
  Кривая без истории:10394
  Кривая без истории:10395
  Кривая без истории:10396
  Кривая без истории:10397
  Кривая без истории:10398
  Кривая без истории:10399
  Кривая без истории:10400
  Кривая без истории:10401
  Кривая без истории:10402
  Кривая без истории:10403
  Кривая без истории:10404
  Кривая без истории:10405
  Кривая без истории:10406
  Кривая без истории:10407
  Кривая без истории:10408
  Кривая без истории:10409
  Кривая без истории:10410
  Кривая без истории:10411
  Кривая без истории:10412
  Кривая без истории:10413
  Кривая без истории:10414
  Кривая без истории:10415
  Кривая без истории:10416
  Кривая без истории:10417
  Кривая без истории:10418
  Кривая без истории:10419
  Кривая без истории:10420
  Кривая без истории:10421
  Кривая без истории:10422
  Кривая без истории:10423
  Кривая без истории:10424
  Кривая без истории:10425
  Кривая без истории:10426
  Кривая без истории:10427
  Кривая без истории:10428
  Кривая без истории:10429
  Кривая без истории:10430
  Кривая без истории:10431
  Кривая без истории:10432
  Кривая без истории:10433
  Кривая без истории:10434
  Кривая без истории:10435
  Кривая без истории:10436
  Кривая без истории:10437
  Кривая без истории:10438
  Кривая без истории:10439
  Кривая без истории:10440
  Кривая без истории:10441
  Кривая без истории:10442
  Кривая без истории:10443
  Кривая без истории:10444
  Кривая без истории:10445
  Кривая без истории:10446
  Кривая без истории:10447
  Кривая без истории:10448
  Кривая без истории:10449
  Кривая без истории:10450
  Кривая без истории:10451
  Кривая без истории:10452
  Кривая без истории:10453
  Кривая без истории:10454
  Кривая без истории:10455
  Кривая без истории:10456
  Кривая без истории:10457
  Кривая без истории:10458
  Кривая без истории:10459
  Кривая без истории:10460
  Кривая без истории:10461
  Кривая без истории:10462
  Кривая без истории:10463
  Кривая без истории:10464
  Кривая без истории:10465
  Кривая без истории:10466
  Кривая без истории:10467
  Кривая без истории:10468
  Кривая без истории:10469
  Кривая без истории:10470
  Кривая без истории:10471
  Кривая без истории:10472
  Кривая без истории:10473
  Кривая без истории:10474
  Кривая без истории:10475
  Кривая без истории:10476
  Кривая без истории:10477
  Кривая без истории:10478
  Кривая без истории:10479
  Кривая без истории:10480
  Кривая без истории:10481
  Кривая без истории:10482
  Кривая без истории:10483
  Кривая без истории:10484
  Кривая без истории:10485
  Кривая без истории:10486
  Кривая без истории:10487
  Кривая без истории:10488
  Кривая без истории:10489
  Кривая без истории:10490
  Кривая без истории:10491
  Кривая без истории:10492
  Кривая без истории:10493
  Кривая без истории:10494
  Кривая без истории:10495
  Кривая без истории:10496
  Кривая без истории:10497
  Кривая без истории:10498
  Кривая без истории:10499
  Кривая без истории:10500
  Кривая без истории:10501
  Кривая без истории:10502
  Кривая без истории:10503
  Кривая без истории:10504
  Кривая без истории:10505
  Кривая без истории:10506
  Кривая без истории:10507
  Кривая без истории:10508
  Кривая без истории:10509
  Кривая без истории:10510
  Кривая без истории:10511
  Кривая без истории:10512
  Кривая без истории:10513
  Кривая без истории:10514
  Кривая без истории:10515
  Кривая без истории:10516
  Кривая без истории:10517
  Кривая без истории:10518
  Кривая без истории:10519
  Кривая без истории:10520
  Кривая без истории:10521
  Кривая без истории:10522
  Кривая без истории:10523
  Кривая без истории:10524
  Кривая без истории:10525
  Кривая без истории:10526
  Кривая без истории:10527
  Кривая без истории:10528
  Кривая без истории:10529
  Кривая без истории:10530
  Кривая без истории:10531
  Кривая без истории:10532
  Кривая без истории:10533
  Кривая без истории:10534
  Кривая без истории:10535
  Кривая без истории:10536
  Кривая без истории:10537
  Кривая без истории:10538
  Кривая без истории:10539
  Кривая без истории:10540
  Кривая без истории:10541
  Кривая без истории:10542
  Кривая без истории:10543
  Кривая без истории:10544
  Кривая без истории:10545
  Кривая без истории:10546
  Кривая без истории:10547
  Кривая без истории:10548
  Кривая без истории:10549
  Кривая без истории:10550
  Кривая без истории:10551
  Кривая без истории:10552
  Кривая без истории:10553
  Кривая без истории:10554
  Кривая без истории:10555
  Кривая без истории:10556
  Кривая без истории:10557
  Кривая без истории:10558
  Кривая без истории:10559
  Кривая без истории:10560
  Кривая без истории:10561
  Кривая без истории:10562
  Кривая без истории:10563
  Кривая без истории:10564
  Кривая без истории:10565
  Кривая без истории:10566
  Кривая без истории:10567
  Кривая без истории:10568
  Кривая без истории:10569
  Кривая без истории:10570
  Кривая без истории:10571
  Кривая без истории:10572
  Кривая без истории:10573
  Кривая без истории:10574
  Кривая без истории:10575
  Кривая без истории:10576
  Кривая без истории:10577
  Кривая без истории:10578
  Кривая без истории:10579
  Кривая без истории:10580
  Кривая без истории:10581
  Кривая без истории:10582
  Кривая без истории:10583
  Кривая без истории:10584
  Кривая без истории:10585
  Кривая без истории:10586
  Кривая без истории:10587
  Кривая без истории:10588
  Кривая без истории:10589
  Кривая без истории:10590
  Кривая без истории:10591
  Кривая без истории:10592
  Кривая без истории:10593
  Кривая без истории:10594
  Кривая без истории:10595
  Кривая без истории:10596
  Кривая без истории:10597
  Кривая без истории:10598
  Кривая без истории:10599
  Кривая без истории:10600
  Кривая без истории:10601
  Кривая без истории:10602
  Кривая без истории:10603
  Кривая без истории:10604
  Кривая без истории:10605
  Кривая без истории:10606
  Кривая без истории:10607
  Кривая без истории:10608
  Кривая без истории:10609
  Кривая без истории:10610
  Кривая без истории:10611
  Кривая без истории:10612
  Кривая без истории:10613
  Кривая без истории:10614
  Кривая без истории:10615
  Кривая без истории:10616
  Кривая без истории:10617
  Кривая без истории:10618
  Кривая без истории:10619
  Кривая без истории:10620
  Кривая без истории:10621
  Кривая без истории:10622
  Кривая без истории:10623
  Кривая без истории:10624
  Кривая без истории:10625
  Кривая без истории:10626
  Кривая без истории:10627
  Кривая без истории:10628
  Кривая без истории:10629
  Кривая без истории:10630
  Кривая без истории:10631
  Кривая без истории:10632
  Кривая без истории:10633
  Кривая без истории:10634
  Кривая без истории:10635
  Кривая без истории:10636
  Кривая без истории:10637
  Кривая без истории:10638
  Кривая без истории:10639
  Кривая без истории:10640
  Кривая без истории:10641
  Кривая без истории:10642
  Кривая без истории:10643
  Кривая без истории:10644
  Кривая без истории:10645
  Кривая без истории:10646
  Кривая без истории:10647
  Кривая без истории:10648
  Кривая без истории:10649
  Кривая без истории:10650
  Кривая без истории:10651
  Кривая без истории:10652
  Кривая без истории:10653
  Кривая без истории:10654
  Кривая без истории:10655
  Кривая без истории:10656
  Кривая без истории:10657
  Кривая без истории:10658
  Кривая без истории:10659
  Кривая без истории:10660
  Кривая без истории:10661
  Кривая без истории:10662
  Кривая без истории:10663
  Кривая без истории:10664
  Кривая без истории:10665
  Кривая без истории:10666
  Кривая без истории:10667
  Кривая без истории:10668
  Кривая без истории:10669
  Кривая без истории:10670
  Кривая без истории:10671
  Кривая без истории:10672
  Кривая без истории:10673
  Кривая без истории:10674
  Кривая без истории:10675
  Кривая без истории:10676
  Кривая без истории:10677
  Кривая без истории:10678
  Кривая без истории:10679
  Кривая без истории:10680
  Кривая без истории:10681
  Кривая без истории:10682
  Кривая без истории:10683
  Кривая без истории:10684
  Кривая без истории:10685
  Кривая без истории:10686
  Кривая без истории:10687
  Кривая без истории:10688
  Кривая без истории:10689
  Кривая без истории:10690
  Кривая без истории:10691
  Кривая без истории:10692
  Кривая без истории:10693
  Кривая без истории:10694
  Кривая без истории:10695
  Кривая без истории:10696
  Кривая без истории:10697
  Кривая без истории:10698
  Кривая без истории:10699
  Кривая без истории:10700
  Кривая без истории:10701
  Кривая без истории:10702
  Кривая без истории:10703
  Кривая без истории:10704
  Кривая без истории:10705
  Кривая без истории:10706
  Кривая без истории:10707
  Кривая без истории:10708
  Кривая без истории:10709
  Кривая без истории:10710
  Кривая без истории:10711
  Кривая без истории:10712
  Кривая без истории:10713
  Кривая без истории:10714
  Кривая без истории:10715
  Кривая без истории:10716
  Кривая без истории:10717
  Кривая без истории:10718
  Кривая без истории:10719
  Кривая без истории:10720
  Кривая без истории:10721
  Кривая без истории:10722
  Кривая без истории:10723
  Кривая без истории:10724
  Кривая без истории:10725
  Кривая без истории:10726
  Кривая без истории:10727
  Кривая без истории:10728
  Кривая без истории:10729
  Кривая без истории:10730
  Кривая без истории:10731
  Кривая без истории:10732
  Кривая без истории:10733
  Кривая без истории:10734
  Кривая без истории:10735
  Кривая без истории:10736
  Кривая без истории:10737
  Кривая без истории:10738
  Кривая без истории:10739
  Кривая без истории:10740
  Кривая без истории:10741
  Кривая без истории:10742
  Кривая без истории:10743
  Кривая без истории:10744
  Кривая без истории:10745
  Кривая без истории:10746
  Кривая без истории:10747
  Кривая без истории:10748
  Кривая без истории:10749
  Кривая без истории:10750
  Кривая без истории:10751
  Кривая без истории:10752
  Кривая без истории:10753
  Кривая без истории:10754
  Кривая без истории:10755
  Кривая без истории:10756
  Кривая без истории:10757
  Кривая без истории:10758
  Кривая без истории:10759
  Кривая без истории:10760
  Кривая без истории:10761
  Кривая без истории:10762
